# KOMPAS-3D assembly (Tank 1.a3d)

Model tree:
1. Plane XY
2. Plane ZX
3. Plane ZY
4. X Axis
5. Y Axis
6. Z Axis
7. Origin
8. Attachment Point:1
9. Attachment Point:2
10. Attachment Point:3
11. Attachment Point:4  (labels: C:\Program Files\ASCON\KOMPAS-3D V10\Sys\graphic.lyt; Tank 1; Tank 1.spw; Tank 1.a3d)

Referenced files in C:\Documents and Settings\kashirsky\Мои документы\Camtasia Studio\Pipelines3D\Tanks\: Tank 1.m3d, Piping_Flange_50_1000.m3d, Piping_Flange_150_1000.m3d, Tank 1.a3d, Tank 1.spw, Tanks_step 1.a3d, Tanks_step 1.spw, Tanks_step 2.a3d, Tanks_step 3.a3d, Tanks_step 4.a3d
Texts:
  Tank 1
  Three Point Plane
  Plane at Angle
  Line and Point Plane
  Axis through Two Vertices
  Axis of Feature
  Axis of Conical Surface
  Axis through Edge
  Trim by Surface
  Trim by Sketch
  Intersection Axis of Two Planes
  Two Line Plane
  Line and Face Plane
  Pattern by Sample
  Point in CM
  Feature with No History
  Linear Dimension from Line to Point
  Surface Finish Symbol
  Geometric Tolerance Symbol
  Текст на чертеже
  Линия-выноска #1
  Линия-выноска #2
  Линия-выноска #3
  Отклонения формы и база
  Марка координационной оси
  Марка/позиционное обозначение с линией-выноской
  Марка/позиционное обозначение на линии
  Марка/позиционное обозначение без линии-выноски
  Steel ASTM A295
  Flange Dn 50
  Flange Dn 150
